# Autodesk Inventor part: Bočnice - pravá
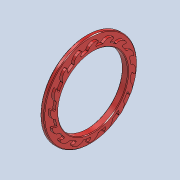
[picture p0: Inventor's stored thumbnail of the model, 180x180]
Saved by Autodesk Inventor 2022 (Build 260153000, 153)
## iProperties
Created: 2025-05
Part Number: Bočnice - pravá
Material: Všeobecné
Document SubType Name: Modeling
Designer: jbart
Density: 1 g/cm^3
Appearance: Oranžovo-červená
Mass: 6708.64 g
Surface Area: 5461.61 cm^2
Volume: 6708.64 cm^3
Author: jbart
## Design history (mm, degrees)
sketch "Náčrt1"
  geometry: L1 (0, 0)-(30, 0); L2 (0, 360)-(30, 360); L3 (30, 360)-(30, 270); L4 (30, 270)-(0, 270); L5 (0, 270)-(0, 360); 2 further points
  constraints: 10 end point, 2 horizontal, 2 midpoint, 2 parallel, 2 vertical alignment, 1 perpendicular
  dimensions: "d0" = 30 distance of L1.start L1.end; "d1" = 540 diameter of L4 L1; "d2" = 720 diameter of L2 L1
revolve "Rotace1" sketch "Náčrt1" stored, may be unused: angle "d3" = 90 deg
sketch "Náčrt2"
  geometry: C1 r 270 at (0, 0); C2 r 330 at (0, 0); A1 r 294.238 centre (0, 0) between (291.443, 40.463) and (280.604, 88.53); A2 r 5 centre (256.05, 153.365) between (253.774, 148.913) and (255.979, 148.365); A3 r 40 centre (55.44, 281.403) between (36.91, 316.853) and (20.243, 300.408); A4 r 60 centre (15.989, 269.526) between (36.286, 325.989) and (-39.113, 293.271); A5 r 5 centre (34.594, 321.284) between (36.91, 316.853) and (36.286, 325.989); A6 r 5 centre (24.643, 298.032) between (20.243, 300.408) and (25.592, 293.123); A7 r 294.238 centre (0, 0) between (74.147, 284.743) and (25.592, 293.123); A8 r 5 centre (-43.704, 295.25) between (-40.463, 291.443) and (-39.113, 293.271); A9 r 294.238 centre (0, 0) between (-40.463, 291.443) and (-88.53, 280.604); A10 r 5 centre (-91.285, 284.777) between (-96.259, 285.288) and (-88.53, 280.604); A11 r 40 centre (-56.468, 281.199) between (-87.153, 306.859) and (-96.259, 285.288); A12 r 5 centre (-90.989, 310.066) between (-87.153, 306.859) and (-91.227, 315.06); A13 r 5 centre (-295.25, -43.704) between (-291.443, -40.463) and (-293.271, -39.113); A14 r 294.238 centre (0, 0) between (-291.443, -40.463) and (-280.604, -88.53); A15 r 5 centre (-310.066, -90.989) between (-306.859, -87.153) and (-315.06, -91.227); A16 r 5 centre (-284.777, -91.285) between (-285.288, -96.259) and (-280.604, -88.53); A17 r 40 centre (-281.199, -56.468) between (-306.859, -87.153) and (-285.288, -96.259); A18 r 60 centre (-255.128, -88.371) between (-315.06, -91.227) and (-255.979, -148.365); A19 r 5 centre (-256.05, -153.365) between (-253.774, -148.913) and (-255.979, -148.365); A20 r 5 centre (-289.5, 72.61) between (-284.743, 74.147) and (-285.915, 76.095); A21 r 60 centre (-242.891, 117.915) between (-287.289, 158.274) and (-285.915, 76.095); A22 r 5 centre (-283.589, 154.911) between (-278.609, 155.355) and (-287.289, 158.274); A23 r 40 centre (-238.767, 158.909) between (-278.609, 155.355) and (-269.794, 133.664); A24 r 5 centre (-265.916, 136.819) between (-269.794, 133.664) and (-261.017, 135.817); A25 r 60 centre (-269.526, 15.989) between (-325.989, 36.286) and (-293.271, -39.113); A26 r 5 centre (-298.032, 24.643) between (-300.408, 20.243) and (-293.123, 25.592); A27 r 40 centre (-281.403, 55.44) between (-316.853, 36.91) and (-300.408, 20.243); A28 r 5 centre (-321.284, 34.594) between (-316.853, 36.91) and (-325.989, 36.286); A29 r 294.238 centre (0, 0) between (-284.743, 74.147) and (-293.123, 25.592); A30 r 294.238 centre (0, 0) between (-234.693, 177.47) and (-261.017, 135.817); A31 r 5 centre (-72.61, -289.5) between (-74.147, -284.743) and (-76.095, -285.915); A32 r 294.238 centre (0, 0) between (-74.147, -284.743) and (-25.592, -293.123); A33 r 5 centre (43.704, -295.25) between (40.463, -291.443) and (39.113, -293.271); A34 r 5 centre (-24.643, -298.032) between (-20.243, -300.408) and (-25.592, -293.123); A35 r 40 centre (-55.44, -281.403) between (-36.91, -316.853) and (-20.243, -300.408); A36 r 5 centre (-34.594, -321.284) between (-36.91, -316.853) and (-36.286, -325.989); A37 r 60 centre (-15.989, -269.526) between (-36.286, -325.989) and (39.113, -293.271); A38 r 294.238 centre (0, 0) between (40.463, -291.443) and (88.53, -280.604); A39 r 5 centre (91.285, -284.777) between (96.259, -285.288) and (88.53, -280.604); A40 r 40 centre (56.468, -281.199) between (87.153, -306.859) and (96.259, -285.288); A41 r 5 centre (90.989, -310.066) between (87.153, -306.859) and (91.227, -315.06); A42 r 60 centre (88.371, -255.128) between (91.227, -315.06) and (148.365, -255.979); A43 r 5 centre (-177.87, -239.677) between (-177.47, -234.693) and (-179.717, -235.031); A44 r 294.238 centre (0, 0) between (-253.774, -148.913) and (-225.365, -189.173); A45 r 5 centre (-228.166, -193.316) between (-226.735, -198.106) and (-225.365, -189.173); A46 r 40 centre (-238.185, -159.78) between (-250.148, -197.949) and (-226.735, -198.106); A47 r 5 centre (-251.644, -202.72) between (-250.148, -197.949) and (-256.167, -204.851); A48 r 60 centre (-201.89, -179.278) between (-256.167, -204.851) and (-179.717, -235.031); A49 r 294.238 centre (0, 0) between (-177.47, -234.693) and (-135.817, -261.017); A50 r 5 centre (-136.819, -265.916) between (-133.664, -269.794) and (-135.817, -261.017); A51 r 40 centre (-158.909, -238.767) between (-155.355, -278.609) and (-133.664, -269.794); A52 r 5 centre (-154.911, -283.589) between (-155.355, -278.609) and (-158.274, -287.289); A53 r 60 centre (-117.915, -242.891) between (-158.274, -287.289) and (-76.095, -285.915); A54 r 5 centre (265.916, -136.819) between (269.794, -133.664) and (261.017, -135.817); A55 r 294.238 centre (0, 0) between (234.693, -177.47) and (261.017, -135.817); A56 r 5 centre (239.677, -177.87) between (234.693, -177.47) and (235.031, -179.717); A57 r 5 centre (193.316, -228.166) between (198.106, -226.735) and (189.173, -225.365); A58 r 60 centre (179.278, -201.89) between (204.851, -256.167) and (235.031, -179.717); A59 r 294.238 centre (0, 0) between (148.913, -253.774) and (189.173, -225.365); A60 r 5 centre (202.72, -251.644) between (197.949, -250.148) and (204.851, -256.167); A61 r 5 centre (153.365, -256.05) between (148.913, -253.774) and (148.365, -255.979); A62 r 40 centre (159.78, -238.185) between (197.949, -250.148) and (198.106, -226.735); A63 r 40 centre (238.767, -158.909) between (278.609, -155.355) and (269.794, -133.664); A64 r 294.238 centre (0, 0) between (284.743, -74.147) and (293.123, -25.592)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; 2 further points
  constraints: 192 point on circle, 98 centre point, 5 tangent, 4 coincident, 257 other
  dimensions: "d6" = 660 diameter of C2; "d7" = 5 radius of A5; "d8" = 40 radius of A3; "d9" = 60 radius of A4; "d10" = 5 radius of A6; "d11" = 5 radius of A8; "d12" = 360 deg dimension on C1.centre A8.centre (derived); "d13" = 540 diameter of C1
extrude "Vysunutí1" join sketch "Náčrt2" distance "d14" = 20; taper "d15" = 0 deg
chamfer "Zkosení1" distance "d16" = 5; stored, may be unused: second distance "d17" = 2, angle "d18" = 45 deg
node "Těleso1"
